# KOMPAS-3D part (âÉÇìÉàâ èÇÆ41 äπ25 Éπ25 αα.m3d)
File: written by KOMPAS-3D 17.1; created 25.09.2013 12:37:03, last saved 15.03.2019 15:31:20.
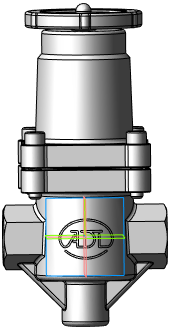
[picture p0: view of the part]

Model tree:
1. Операция без истории:3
